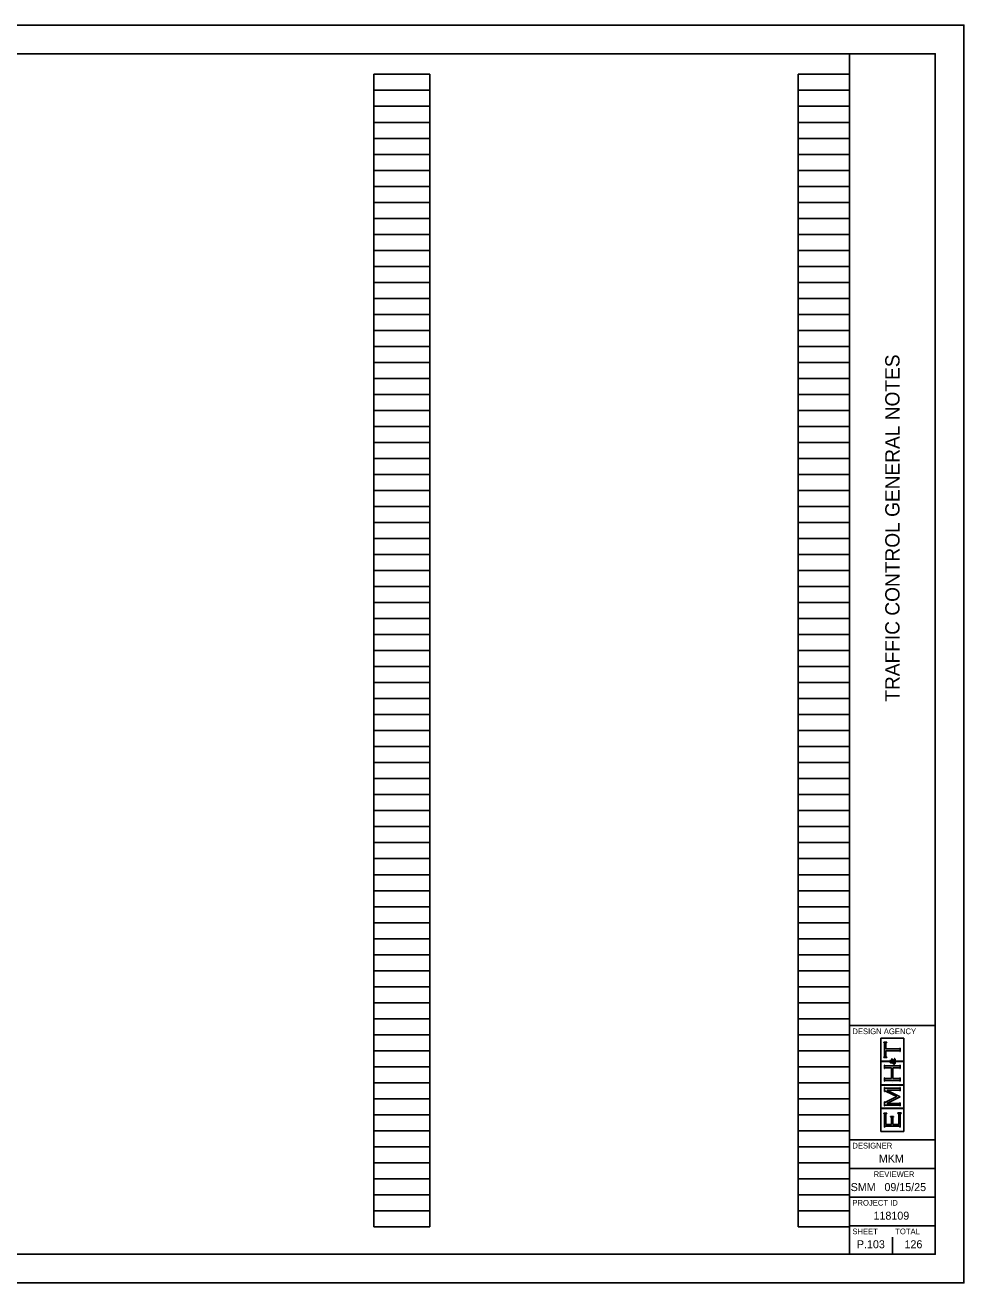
# Model space of a CAD drawing. Extents: x 0 to 34, y 0 to 22.
# Drawn here: x 17.58 to 34, y 0 to 22 of the extents above; entities that cross this region are included whole.
import ezdxf

# ---------------------------------------------------------------- set-up
doc = ezdxf.new("R2010")
doc.units = 0
for name, color, linetype in [('SH_Border', 7, 'Continuous'), ('SH_Cut_Line', 7, 'Continuous'), ('SH_Data', 7, 'Continuous')]:
    doc.layers.add(name, color=color, linetype=linetype)

msp = doc.modelspace()

# ---------------------------------------------------------------- linework, layer by layer
at = {"layer": 'SH_Border'}
for p, q in [((32, 0.5), (32, 21.5)), ((32, 4.5), (33.5, 4.5)), ((32, 2.5), (33.5, 2.5)), ((32, 2), (33.5, 2)), ((32, 1.5), (33.5, 1.5)), ((32, 1), (33.5, 1))]:
    msp.add_line(p, q, dxfattribs=at)
msp.add_lwpolyline([(1.5, 21.5), (33.5, 21.5), (33.5, 0.5), (1.5, 0.5)], close=True, dxfattribs=at)
at = {"layer": 'SH_Cut_Line'}
msp.add_lwpolyline([(0, 0), (34, 0), (34, 22), (0, 22)], close=True, dxfattribs=at)
at = {"layer": 'SH_Data'}
for p, q in [((23.68, 0.98), (23.68, 21.14)), ((23.68, 21.14), (24.66, 21.14)), ((24.66, 0.98), (24.66, 21.14)), ((31.1, 0.98), (31.1, 21.14)), ((31.1, 21.14), (32, 21.14)), ((32, 0.98), (32, 21.14)), ((23.68, 20.86), (24.66, 20.86)), ((31.1, 20.86), (32, 20.86)), ((23.68, 20.58), (24.66, 20.58)), ((31.1, 20.58), (32, 20.58)), ((23.68, 20.3), (24.66, 20.3)), ((31.1, 20.3), (32, 20.3)), ((23.68, 20.02), (24.66, 20.02)), ((31.1, 20.02), (32, 20.02)), ((23.68, 19.74), (24.66, 19.74)), ((31.1, 19.74), (32, 19.74)), ((23.68, 19.46), (24.66, 19.46)), ((31.1, 19.46), (32, 19.46)), ((23.68, 19.18), (24.66, 19.18)), ((31.1, 19.18), (32, 19.18)), ((23.68, 18.9), (24.66, 18.9)), ((31.1, 18.9), (32, 18.9)), ((23.68, 18.62), (24.66, 18.62)), ((31.1, 18.62), (32, 18.62)), ((23.68, 18.34), (24.66, 18.34)), ((31.1, 18.34), (32, 18.34)), ((23.68, 18.06), (24.66, 18.06)), ((31.1, 18.06), (32, 18.06)), ((23.68, 17.78), (24.66, 17.78)), ((31.1, 17.78), (32, 17.78)), ((23.68, 17.5), (24.66, 17.5)), ((31.1, 17.5), (32, 17.5)), ((23.68, 17.22), (24.66, 17.22)), ((31.1, 17.22), (32, 17.22)), ((23.68, 16.94), (24.66, 16.94)), ((31.1, 16.94), (32, 16.94)), ((23.68, 16.66), (24.66, 16.66)), ((31.1, 16.66), (32, 16.66)), ((23.68, 16.38), (24.66, 16.38)), ((31.1, 16.38), (32, 16.38)), ((23.68, 16.1), (24.66, 16.1)), ((31.1, 16.1), (32, 16.1)), ((23.68, 15.82), (24.66, 15.82)), ((31.1, 15.82), (32, 15.82)), ((23.68, 15.54), (24.66, 15.54)), ((31.1, 15.54), (32, 15.54)), ((23.68, 15.26), (24.66, 15.26)), ((31.1, 15.26), (32, 15.26)), ((23.68, 14.98), (24.66, 14.98)), ((31.1, 14.98), (32, 14.98)), ((23.68, 14.7), (24.66, 14.7)), ((31.1, 14.7), (32, 14.7)), ((23.68, 14.42), (24.66, 14.42)), ((31.1, 14.42), (32, 14.42)), ((23.68, 14.14), (24.66, 14.14)), ((31.1, 14.14), (32, 14.14)), ((23.68, 13.86), (24.66, 13.86)), ((31.1, 13.86), (32, 13.86)), ((23.68, 13.58), (24.66, 13.58)), ((31.1, 13.58), (32, 13.58)), ((23.68, 13.3), (24.66, 13.3)), ((31.1, 13.3), (32, 13.3)), ((23.68, 13.02), (24.66, 13.02)), ((31.1, 13.02), (32, 13.02)), ((23.68, 12.74), (24.66, 12.74)), ((31.1, 12.74), (32, 12.74)), ((23.68, 12.46), (24.66, 12.46)), ((31.1, 12.46), (32, 12.46)), ((23.68, 12.18), (24.66, 12.18)), ((31.1, 12.18), (32, 12.18)), ((23.68, 11.9), (24.66, 11.9)), ((31.1, 11.9), (32, 11.9)), ((23.68, 11.62), (24.66, 11.62)), ((31.1, 11.62), (32, 11.62)), ((23.68, 11.34), (24.66, 11.34)), ((31.1, 11.34), (32, 11.34)), ((23.68, 11.06), (24.66, 11.06)), ((31.1, 11.06), (32, 11.06)), ((23.68, 10.78), (24.66, 10.78)), ((31.1, 10.78), (32, 10.78)), ((23.68, 10.5), (24.66, 10.5)), ((31.1, 10.5), (32, 10.5)), ((23.68, 10.22), (24.66, 10.22)), ((31.1, 10.22), (32, 10.22)), ((23.68, 9.94), (24.66, 9.94)), ((31.1, 9.94), (32, 9.94)), ((23.68, 9.66), (24.66, 9.66)), ((31.1, 9.66), (32, 9.66)), ((23.68, 9.38), (24.66, 9.38)), ((31.1, 9.38), (32, 9.38)), ((23.68, 9.1), (24.66, 9.1)), ((31.1, 9.1), (32, 9.1)), ((23.68, 8.82), (24.66, 8.82)), ((31.1, 8.82), (32, 8.82)), ((23.68, 8.54), (24.66, 8.54)), ((31.1, 8.54), (32, 8.54)), ((23.68, 8.26), (24.66, 8.26)), ((31.1, 8.26), (32, 8.26)), ((23.68, 7.98), (24.66, 7.98)), ((31.1, 7.98), (32, 7.98)), ((23.68, 7.7), (24.66, 7.7)), ((31.1, 7.7), (32, 7.7)), ((23.68, 7.42), (24.66, 7.42)), ((31.1, 7.42), (32, 7.42)), ((23.68, 7.14), (24.66, 7.14)), ((31.1, 7.14), (32, 7.14)), ((23.68, 6.86), (24.66, 6.86)), ((31.1, 6.86), (32, 6.86)), ((23.68, 6.58), (24.66, 6.58)), ((31.1, 6.58), (32, 6.58)), ((23.68, 6.3), (24.66, 6.3)), ((31.1, 6.3), (32, 6.3)), ((23.68, 6.02), (24.66, 6.02)), ((31.1, 6.02), (32, 6.02)), ((23.68, 5.74), (24.66, 5.74)), ((31.1, 5.74), (32, 5.74)), ((23.68, 5.46), (24.66, 5.46)), ((31.1, 5.46), (32, 5.46)), ((23.68, 5.18), (24.66, 5.18)), ((31.1, 5.18), (32, 5.18)), ((23.68, 4.9), (24.66, 4.9)), ((31.1, 4.9), (32, 4.9)), ((23.68, 4.62), (24.66, 4.62)), ((31.1, 4.62), (32, 4.62)), ((23.68, 4.34), (24.66, 4.34)), ((31.1, 4.34), (32, 4.34)), ((32.952, 4.279), (32.547, 4.279)), ((32.547, 4.279), (32.547, 3.875)), ((32.598, 4.204), (32.598, 4.211)), ((32.598, 4.211), (32.65, 4.211)), ((32.603, 4.203), (32.598, 4.204)), ((32.606, 4.201), (32.603, 4.203)), ((32.608, 4.199), (32.606, 4.201)), ((32.61, 4.196), (32.608, 4.199)), ((32.611, 4.192), (32.61, 4.196)), ((32.611, 4.187), (32.611, 4.192)), ((32.611, 3.968), (32.611, 4.187)), ((32.638, 4.196), (32.637, 4.192)), ((32.637, 4.192), (32.637, 4.187)), ((32.637, 4.187), (32.637, 4.093)), ((32.64, 4.199), (32.638, 4.196)), ((32.642, 4.201), (32.64, 4.199)), ((32.645, 4.203), (32.642, 4.201)), ((32.65, 4.204), (32.645, 4.203)), ((32.65, 4.211), (32.65, 4.204)), ((32.952, 3.875), (32.952, 4.279)), ((23.68, 4.06), (24.66, 4.06)), ((31.1, 4.06), (32, 4.06)), ((32.61, 3.958), (32.611, 3.962)), ((32.611, 3.962), (32.611, 3.968)), ((32.637, 4.093), (32.864, 4.093)), ((32.864, 4.061), (32.637, 4.061)), ((32.637, 4.061), (32.637, 3.968)), ((32.637, 3.968), (32.637, 3.962)), ((32.637, 3.962), (32.638, 3.958)), ((32.864, 4.093), (32.869, 4.093)), ((32.87, 4.061), (32.864, 4.061)), ((32.869, 4.093), (32.873, 4.094)), ((32.874, 4.06), (32.87, 4.061)), ((32.873, 4.094), (32.876, 4.096)), ((32.876, 4.059), (32.874, 4.06)), ((32.876, 4.096), (32.878, 4.097)), ((32.878, 4.057), (32.876, 4.059)), ((32.878, 4.097), (32.88, 4.101)), ((32.88, 4.053), (32.878, 4.057)), ((32.88, 4.101), (32.881, 4.106)), ((32.881, 4.048), (32.88, 4.053)), ((32.881, 4.106), (32.888, 4.106)), ((32.888, 4.048), (32.881, 4.048)), ((32.888, 4.106), (32.888, 4.048)), ((23.68, 3.78), (24.66, 3.78)), ((31.1, 3.78), (32, 3.78)), ((32.547, 3.875), (32.696, 3.875)), ((32.696, 3.869), (32.547, 3.869)), ((32.547, 3.869), (32.547, 3.465)), ((32.598, 3.95), (32.603, 3.951)), ((32.598, 3.944), (32.598, 3.95)), ((32.65, 3.944), (32.598, 3.944)), ((32.603, 3.951), (32.606, 3.953)), ((32.606, 3.953), (32.608, 3.955)), ((32.608, 3.955), (32.61, 3.958)), ((32.611, 3.749), (32.611, 3.807)), ((32.611, 3.807), (32.617, 3.807)), ((32.617, 3.749), (32.611, 3.749)), ((32.617, 3.807), (32.619, 3.802)), ((32.618, 3.754), (32.617, 3.749)), ((32.62, 3.758), (32.618, 3.754)), ((32.619, 3.802), (32.62, 3.798)), ((32.62, 3.798), (32.623, 3.797)), ((32.623, 3.76), (32.62, 3.758)), ((32.623, 3.797), (32.625, 3.795)), ((32.625, 3.761), (32.623, 3.76)), ((32.625, 3.795), (32.629, 3.794)), ((32.629, 3.762), (32.625, 3.761)), ((32.629, 3.794), (32.635, 3.794)), ((32.635, 3.762), (32.629, 3.762)), ((32.635, 3.794), (32.864, 3.794)), ((32.732, 3.762), (32.635, 3.762)), ((32.638, 3.958), (32.64, 3.955)), ((32.64, 3.955), (32.642, 3.953)), ((32.642, 3.953), (32.645, 3.951)), ((32.645, 3.951), (32.65, 3.95)), ((32.65, 3.95), (32.65, 3.944)), ((32.696, 3.875), (32.696, 3.869)), ((32.703, 3.879), (32.705, 3.883)), ((32.703, 3.873), (32.703, 3.879)), ((32.703, 3.868), (32.703, 3.873)), ((32.705, 3.863), (32.703, 3.868)), ((32.705, 3.883), (32.708, 3.887)), ((32.708, 3.858), (32.705, 3.863)), ((32.708, 3.887), (32.711, 3.89)), ((32.709, 3.879), (32.708, 3.876)), ((32.708, 3.876), (32.708, 3.873)), ((32.708, 3.873), (32.708, 3.869)), ((32.708, 3.869), (32.71, 3.866)), ((32.712, 3.853), (32.708, 3.858)), ((32.712, 3.881), (32.709, 3.879)), ((32.71, 3.866), (32.712, 3.864)), ((32.711, 3.89), (32.715, 3.892)), ((32.714, 3.883), (32.712, 3.881)), ((32.712, 3.864), (32.715, 3.862)), ((32.718, 3.85), (32.712, 3.853)), ((32.716, 3.884), (32.714, 3.883)), ((32.715, 3.892), (32.72, 3.892)), ((32.715, 3.862), (32.718, 3.861)), ((32.72, 3.884), (32.716, 3.884)), ((32.718, 3.861), (32.721, 3.861)), ((32.726, 3.85), (32.718, 3.85)), ((32.72, 3.892), (32.725, 3.892)), ((32.724, 3.884), (32.72, 3.884)), ((32.721, 3.861), (32.723, 3.861)), ((32.723, 3.861), (32.725, 3.862)), ((32.728, 3.882), (32.724, 3.884)), ((32.725, 3.892), (32.729, 3.89)), ((32.725, 3.862), (32.728, 3.862)), ((32.729, 3.85), (32.726, 3.85)), ((32.731, 3.88), (32.728, 3.882)), ((32.728, 3.862), (32.731, 3.863)), ((32.729, 3.89), (32.732, 3.887)), ((32.731, 3.85), (32.729, 3.85)), ((32.734, 3.877), (32.731, 3.88)), ((32.731, 3.863), (32.735, 3.865)), ((32.734, 3.851), (32.731, 3.85)), ((32.732, 3.887), (32.736, 3.883)), ((32.732, 3.572), (32.732, 3.762)), ((32.737, 3.872), (32.734, 3.877)), ((32.737, 3.852), (32.734, 3.851)), ((32.735, 3.865), (32.74, 3.867)), ((32.736, 3.883), (32.74, 3.878)), ((32.74, 3.867), (32.737, 3.872)), ((32.741, 3.853), (32.737, 3.852)), ((32.738, 3.893), (32.738, 3.922)), ((32.738, 3.922), (32.741, 3.922)), ((32.741, 3.893), (32.738, 3.893)), ((32.74, 3.878), (32.744, 3.869)), ((32.741, 3.922), (32.741, 3.918)), ((32.741, 3.918), (32.742, 3.915)), ((32.742, 3.896), (32.741, 3.895)), ((32.741, 3.895), (32.741, 3.893)), ((32.746, 3.855), (32.741, 3.853)), ((32.742, 3.915), (32.743, 3.913)), ((32.743, 3.897), (32.742, 3.896)), ((32.743, 3.913), (32.745, 3.911)), ((32.745, 3.899), (32.743, 3.897)), ((32.744, 3.869), (32.754, 3.875)), ((32.745, 3.911), (32.749, 3.908)), ((32.746, 3.899), (32.745, 3.899)), ((32.748, 3.899), (32.746, 3.899)), ((32.752, 3.844), (32.746, 3.855)), ((32.755, 3.899), (32.748, 3.899)), ((32.749, 3.908), (32.756, 3.904)), ((32.756, 3.86), (32.751, 3.857)), ((32.751, 3.857), (32.754, 3.852)), ((32.757, 3.837), (32.752, 3.844)), ((32.754, 3.875), (32.764, 3.881)), ((32.754, 3.852), (32.757, 3.848)), ((32.763, 3.895), (32.755, 3.899)), ((32.756, 3.904), (32.763, 3.9)), ((32.761, 3.863), (32.756, 3.86)), ((32.757, 3.848), (32.761, 3.845)), ((32.763, 3.833), (32.757, 3.837)), ((32.864, 3.762), (32.759, 3.762)), ((32.759, 3.762), (32.759, 3.572)), ((32.764, 3.865), (32.761, 3.863)), ((32.761, 3.845), (32.765, 3.843)), ((32.763, 3.9), (32.77, 3.896)), ((32.772, 3.887), (32.763, 3.895)), ((32.768, 3.829), (32.763, 3.833)), ((32.764, 3.881), (32.772, 3.887)), ((32.768, 3.867), (32.764, 3.865)), ((32.765, 3.843), (32.769, 3.841)), ((32.774, 3.872), (32.768, 3.867)), ((32.774, 3.827), (32.768, 3.829)), ((32.769, 3.841), (32.773, 3.841)), ((32.77, 3.896), (32.776, 3.891)), ((32.773, 3.841), (32.778, 3.841)), ((32.782, 3.878), (32.774, 3.872)), ((32.779, 3.827), (32.774, 3.827)), ((32.776, 3.891), (32.781, 3.895)), ((32.778, 3.841), (32.782, 3.843)), ((32.779, 3.923), (32.781, 3.926)), ((32.782, 3.922), (32.779, 3.923)), ((32.785, 3.827), (32.779, 3.827)), ((32.781, 3.926), (32.787, 3.924)), ((32.781, 3.895), (32.784, 3.898)), ((32.785, 3.921), (32.782, 3.922)), ((32.786, 3.873), (32.782, 3.878)), ((32.782, 3.843), (32.786, 3.846)), ((32.784, 3.898), (32.786, 3.901)), ((32.786, 3.919), (32.785, 3.921)), ((32.79, 3.829), (32.785, 3.827)), ((32.788, 3.917), (32.786, 3.919)), ((32.786, 3.901), (32.788, 3.904)), ((32.791, 3.886), (32.786, 3.881)), ((32.786, 3.881), (32.791, 3.876)), ((32.788, 3.869), (32.786, 3.873)), ((32.786, 3.846), (32.789, 3.849)), ((32.787, 3.924), (32.792, 3.921)), ((32.789, 3.914), (32.788, 3.917)), ((32.788, 3.904), (32.789, 3.908)), ((32.79, 3.867), (32.788, 3.869)), ((32.789, 3.911), (32.789, 3.914)), ((32.789, 3.908), (32.789, 3.911)), ((32.789, 3.849), (32.791, 3.853)), ((32.791, 3.864), (32.79, 3.867)), ((32.793, 3.834), (32.79, 3.829)), ((32.794, 3.89), (32.791, 3.886)), ((32.791, 3.876), (32.795, 3.87)), ((32.791, 3.861), (32.791, 3.864)), ((32.791, 3.859), (32.791, 3.861)), ((32.791, 3.853), (32.791, 3.859)), ((32.792, 3.921), (32.795, 3.918)), ((32.797, 3.838), (32.793, 3.834)), ((32.796, 3.894), (32.794, 3.89)), ((32.795, 3.918), (32.798, 3.914)), ((32.795, 3.87), (32.797, 3.866)), ((32.798, 3.897), (32.796, 3.894)), ((32.797, 3.866), (32.798, 3.861)), ((32.799, 3.844), (32.797, 3.838)), ((32.798, 3.914), (32.799, 3.91)), ((32.799, 3.901), (32.798, 3.897)), ((32.798, 3.861), (32.799, 3.857)), ((32.799, 3.91), (32.799, 3.905)), ((32.799, 3.905), (32.799, 3.901)), ((32.803, 3.869), (32.799, 3.875)), ((32.799, 3.875), (32.952, 3.875)), ((32.799, 3.857), (32.799, 3.852)), ((32.799, 3.852), (32.799, 3.844)), ((32.952, 3.869), (32.803, 3.869)), ((32.864, 3.794), (32.869, 3.794)), ((32.87, 3.762), (32.864, 3.762)), ((32.869, 3.794), (32.873, 3.795)), ((32.874, 3.761), (32.87, 3.762)), ((32.873, 3.795), (32.876, 3.797)), ((32.876, 3.76), (32.874, 3.761)), ((32.876, 3.797), (32.878, 3.798)), ((32.878, 3.758), (32.876, 3.76)), ((32.878, 3.798), (32.88, 3.802)), ((32.88, 3.754), (32.878, 3.758)), ((32.88, 3.802), (32.881, 3.807)), ((32.881, 3.749), (32.88, 3.754)), ((32.881, 3.807), (32.888, 3.807)), ((32.888, 3.749), (32.881, 3.749)), ((32.888, 3.807), (32.888, 3.749)), ((32.952, 3.465), (32.952, 3.869)), ((32.611, 3.527), (32.611, 3.585)), ((32.611, 3.585), (32.617, 3.585)), ((32.617, 3.527), (32.611, 3.527)), ((32.617, 3.585), (32.619, 3.58)), ((32.618, 3.532), (32.617, 3.527)), ((32.62, 3.536), (32.618, 3.532)), ((32.619, 3.58), (32.62, 3.576)), ((32.62, 3.576), (32.623, 3.574)), ((32.623, 3.537), (32.62, 3.536)), ((32.623, 3.574), (32.625, 3.573)), ((32.625, 3.539), (32.623, 3.537)), ((32.625, 3.573), (32.629, 3.572)), ((32.629, 3.54), (32.625, 3.539)), ((32.629, 3.572), (32.635, 3.572)), ((32.635, 3.54), (32.629, 3.54)), ((32.635, 3.572), (32.732, 3.572)), ((32.864, 3.54), (32.635, 3.54)), ((32.759, 3.572), (32.864, 3.572)), ((32.864, 3.572), (32.87, 3.572)), ((32.87, 3.54), (32.864, 3.54)), ((32.87, 3.572), (32.874, 3.573)), ((32.874, 3.539), (32.87, 3.54)), ((32.874, 3.573), (32.876, 3.574)), ((32.876, 3.538), (32.874, 3.539)), ((32.876, 3.574), (32.878, 3.576)), ((32.878, 3.536), (32.876, 3.538)), ((32.878, 3.576), (32.88, 3.58)), ((32.88, 3.532), (32.878, 3.536)), ((32.88, 3.58), (32.881, 3.585)), ((32.881, 3.527), (32.88, 3.532)), ((32.881, 3.585), (32.888, 3.585)), ((32.888, 3.527), (32.881, 3.527)), ((32.888, 3.585), (32.888, 3.527)), ((23.68, 3.5), (24.66, 3.5)), ((31.1, 3.5), (32, 3.5)), ((32.547, 3.465), (32.952, 3.465)), ((32.952, 3.459), (32.547, 3.459)), ((32.547, 3.459), (32.547, 3.055)), ((32.611, 3.345), (32.611, 3.418)), ((32.611, 3.418), (32.617, 3.418)), ((32.617, 3.345), (32.611, 3.345)), ((32.617, 3.418), (32.619, 3.412)), ((32.62, 3.352), (32.617, 3.345)), ((32.619, 3.412), (32.62, 3.409)), ((32.62, 3.409), (32.623, 3.407)), ((32.622, 3.355), (32.62, 3.352)), ((32.626, 3.355), (32.622, 3.355)), ((32.623, 3.407), (32.625, 3.405)), ((32.625, 3.405), (32.629, 3.405)), ((32.629, 3.355), (32.626, 3.355)), ((32.629, 3.405), (32.635, 3.405)), ((32.633, 3.353), (32.629, 3.355)), ((32.64, 3.35), (32.633, 3.353)), ((32.635, 3.405), (32.864, 3.405)), ((32.825, 3.257), (32.64, 3.35)), ((32.864, 3.373), (32.654, 3.373)), ((32.654, 3.373), (32.888, 3.255)), ((32.75, 3.5), (32.75, 3.5)), ((32.864, 3.405), (32.869, 3.405)), ((32.87, 3.373), (32.864, 3.373)), ((32.869, 3.405), (32.873, 3.405)), ((32.874, 3.372), (32.87, 3.373)), ((32.873, 3.405), (32.876, 3.407)), ((32.876, 3.37), (32.874, 3.372)), ((32.876, 3.407), (32.878, 3.409)), ((32.878, 3.369), (32.876, 3.37)), ((32.878, 3.409), (32.88, 3.412)), ((32.88, 3.365), (32.878, 3.369)), ((32.88, 3.412), (32.881, 3.418)), ((32.881, 3.36), (32.88, 3.365)), ((32.881, 3.418), (32.888, 3.418)), ((32.888, 3.36), (32.881, 3.36)), ((32.888, 3.418), (32.888, 3.36)), ((32.952, 3.055), (32.952, 3.459)), ((23.68, 3.22), (24.66, 3.22)), ((31.1, 3.22), (32, 3.22)), ((32.611, 3.096), (32.611, 3.168)), ((32.611, 3.168), (32.617, 3.168)), ((32.617, 3.096), (32.611, 3.096)), ((32.617, 3.168), (32.62, 3.162)), ((32.618, 3.102), (32.617, 3.096)), ((32.62, 3.105), (32.618, 3.102)), ((32.62, 3.162), (32.622, 3.158)), ((32.623, 3.107), (32.62, 3.105)), ((32.622, 3.158), (32.626, 3.158)), ((32.625, 3.109), (32.623, 3.107)), ((32.629, 3.109), (32.625, 3.109)), ((32.626, 3.158), (32.627, 3.158)), ((32.627, 3.158), (32.633, 3.161)), ((32.635, 3.109), (32.629, 3.109)), ((32.633, 3.161), (32.641, 3.165)), ((32.864, 3.109), (32.635, 3.109)), ((32.641, 3.165), (32.825, 3.257)), ((32.888, 3.255), (32.654, 3.138)), ((32.654, 3.138), (32.864, 3.138)), ((32.864, 3.138), (32.869, 3.138)), ((32.87, 3.109), (32.864, 3.109)), ((32.869, 3.138), (32.873, 3.139)), ((32.874, 3.109), (32.87, 3.109)), ((32.873, 3.139), (32.876, 3.141)), ((32.876, 3.107), (32.874, 3.109)), ((32.876, 3.141), (32.878, 3.143)), ((32.878, 3.105), (32.876, 3.107)), ((32.878, 3.143), (32.88, 3.146)), ((32.88, 3.102), (32.878, 3.105)), ((32.88, 3.146), (32.881, 3.151)), ((32.881, 3.096), (32.88, 3.102)), ((32.881, 3.151), (32.888, 3.151)), ((32.888, 3.096), (32.881, 3.096)), ((32.888, 3.151), (32.888, 3.096)), ((23.68, 2.94), (24.66, 2.94)), ((31.1, 2.94), (32, 2.94)), ((32.547, 3.055), (32.952, 3.055)), ((32.952, 3.049), (32.547, 3.049)), ((32.547, 3.049), (32.547, 2.645)), ((32.598, 2.962), (32.598, 2.969)), ((32.598, 2.969), (32.65, 2.969)), ((32.603, 2.961), (32.598, 2.962)), ((32.606, 2.959), (32.603, 2.961)), ((32.608, 2.957), (32.606, 2.959)), ((32.61, 2.955), (32.608, 2.957)), ((32.611, 2.951), (32.61, 2.955)), ((32.611, 2.945), (32.611, 2.951)), ((32.611, 2.725), (32.611, 2.945)), ((32.64, 2.957), (32.638, 2.955)), ((32.638, 2.955), (32.638, 2.951)), ((32.638, 2.951), (32.638, 2.945)), ((32.638, 2.945), (32.638, 2.77)), ((32.642, 2.959), (32.64, 2.957)), ((32.645, 2.961), (32.642, 2.959)), ((32.65, 2.962), (32.645, 2.961)), ((32.65, 2.969), (32.65, 2.962)), ((32.719, 2.902), (32.719, 2.908)), ((32.719, 2.908), (32.772, 2.908)), ((32.724, 2.901), (32.719, 2.902)), ((32.728, 2.899), (32.724, 2.901)), ((32.729, 2.896), (32.728, 2.899)), ((32.731, 2.894), (32.729, 2.896)), ((32.732, 2.89), (32.731, 2.894)), ((32.732, 2.884), (32.732, 2.89)), ((32.732, 2.77), (32.732, 2.884)), ((32.76, 2.894), (32.759, 2.89)), ((32.759, 2.89), (32.759, 2.884)), ((32.759, 2.884), (32.759, 2.77)), ((32.761, 2.896), (32.76, 2.894)), ((32.763, 2.899), (32.761, 2.896)), ((32.767, 2.901), (32.763, 2.899)), ((32.772, 2.902), (32.767, 2.901)), ((32.772, 2.908), (32.772, 2.902)), ((32.848, 2.965), (32.848, 2.972)), ((32.848, 2.972), (32.901, 2.972)), ((32.853, 2.964), (32.848, 2.965)), ((32.857, 2.962), (32.853, 2.964)), ((32.859, 2.96), (32.857, 2.962)), ((32.86, 2.958), (32.859, 2.96)), ((32.861, 2.953), (32.86, 2.958)), ((32.861, 2.948), (32.861, 2.953)), ((32.861, 2.77), (32.861, 2.948)), ((32.889, 2.957), (32.888, 2.953)), ((32.888, 2.953), (32.888, 2.948)), ((32.888, 2.948), (32.888, 2.725)), ((32.891, 2.96), (32.889, 2.957)), ((32.892, 2.962), (32.891, 2.96)), ((32.896, 2.964), (32.892, 2.962)), ((32.901, 2.965), (32.896, 2.964)), ((32.901, 2.972), (32.901, 2.965)), ((32.952, 2.645), (32.952, 3.049)), ((23.68, 2.66), (24.66, 2.66)), ((31.1, 2.66), (32, 2.66)), ((32.547, 2.645), (32.952, 2.645)), ((32.617, 2.725), (32.611, 2.725)), ((32.619, 2.73), (32.617, 2.725)), ((32.62, 2.734), (32.619, 2.73)), ((32.623, 2.735), (32.62, 2.734)), ((32.625, 2.737), (32.623, 2.735)), ((32.629, 2.738), (32.625, 2.737)), ((32.635, 2.738), (32.629, 2.738)), ((32.864, 2.738), (32.635, 2.738)), ((32.638, 2.77), (32.732, 2.77)), ((32.759, 2.77), (32.861, 2.77)), ((32.87, 2.738), (32.864, 2.738)), ((32.874, 2.737), (32.87, 2.738)), ((32.876, 2.735), (32.874, 2.737)), ((32.878, 2.734), (32.876, 2.735)), ((32.88, 2.73), (32.878, 2.734)), ((32.881, 2.725), (32.88, 2.73)), ((32.888, 2.725), (32.881, 2.725)), ((23.68, 2.38), (24.66, 2.38)), ((31.1, 2.38), (32, 2.38)), ((23.68, 2.1), (24.66, 2.1)), ((31.1, 2.1), (32, 2.1)), ((23.68, 1.82), (24.66, 1.82)), ((31.1, 1.82), (32, 1.82)), ((23.68, 1.54), (24.66, 1.54)), ((31.1, 1.54), (32, 1.54)), ((23.68, 1.26), (24.66, 1.26)), ((31.1, 1.26), (32, 1.26)), ((23.68, 0.98), (24.66, 0.98)), ((31.1, 0.98), (32, 0.98)), ((32.375, 0.675), (32.375, 0.675)), ((32.75, 0.5), (32.75, 0.8))]:
    msp.add_line(p, q, dxfattribs=at)

# ---------------------------------------------------------------- texts
msp.add_text('TRAFFIC CONTROL GENERAL NOTES', height=0.25, rotation=90, dxfattribs=at).set_placement((32.875, 10.166))
for s, height, p in [('DESIGN AGENCY', 0.1, (32.05, 4.35)), ('DESIGNER', 0.1, (32.05, 2.35)), ('MKM', 0.14, (32.513, 2.105)), ('REVIEWER', 0.1, (32.422, 1.85)), ('SMM', 0.14, (32.02, 1.605)), ('09/15/25', 0.14, (32.611, 1.605)), ('PROJECT ID', 0.1, (32.05, 1.35)), ('118109', 0.14, (32.42, 1.105)), ('SHEET', 0.1, (32.05, 0.85)), ('TOTAL', 0.1, (32.8, 0.85)), ('P.103', 0.14, (32.129, 0.605)), ('126', 0.14, (32.962, 0.605))]:
    msp.add_text(s, height=height, dxfattribs=at).set_placement(p)

doc.saveas('drawing.dxf')
